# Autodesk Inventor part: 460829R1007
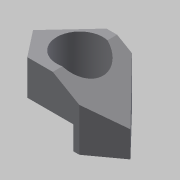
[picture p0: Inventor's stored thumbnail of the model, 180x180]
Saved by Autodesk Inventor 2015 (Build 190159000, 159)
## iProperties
Created: 2016-08
Part Number: 460829R1007
Material: 일반
Document SubType Name: Modeling
Designer: jio
Mass: 542.893 g
Surface Area: 683.408 cm^2
Volume: 542.893 cm^3
Density: 1 g/cm^3
Appearance: 기본값
Author: jio
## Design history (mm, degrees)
sketch "스케치1"
  geometry: L1 (34, 55)-(-9.387, 55); L2 (-9.387, 55)-(-70, -10); L3 (-70, -10)-(-34.842, -55); L4 (-34.842, -55)-(54, -55); L5 (54, -55)-(104.673, -18.184); L6 (104.673, -18.184)-(34, 55); C1 r 39.5 at (0, 0); 1 further point
  constraints: 12 end point, 1 centre point, 1 coincident, 1 horizontal, 1 parallel
  dimensions: "d0" = 79 diameter of C1; "d1" = 99 deg angle of L3 L2; "d2" = 128 deg angle of L4 L3; "d3" = 144 deg angle of L5 L4; "d4" = 134 deg angle of L6 L1; "d5" = 124 horizontal distance of L4.end L2.end; "d6" = 110 vertical distance of L3.end L1.end; "d7" = 45 vertical distance of L3.end L2.end; "d8" = 55 distance from line of L4 point (0, 0); "d9" = 70 horizontal distance of L2.end point (0, 0); "d10" = 104 horizontal distance of L1.start L2.end
extrude "돌출1" new body sketch "스케치1" distance "d11" = 100; taper "d12" = 0 deg
sketch "스케치3"
  geometry: L1 (-70, 15)-(44, 15); L2 (44, 15)-(44, -55); L3 (44, -55)-(-70, -55); L4 (-70, -55)-(-70, 15); 2 further points
  constraints: 8 end point, 2 parallel, 1 horizontal, 1 perpendicular, 1 point on line
  dimensions: "d13" = 70 distance between parallel lines of L1 L3; "d14" = 114 distance between parallel lines of L2 L4; "d15" = 55 distance from line of L3 point (0, 0)
extrude "돌출2" cut sketch "스케치3" distance "d16" = 40; taper "d17" = 0 deg
sketch "스케치4"
  geometry: L1 (43.515, 0)-(139.515, 0); L2 (139.515, 0)-(139.515, -55.426); L3 (139.515, -55.426)-(43.515, 0); 2 further points
  constraints: 6 end point, 1 coincident, 1 horizontal, 1 perpendicular
  dimensions: "d18" = 30 deg angle of L3 L1; "d19" = 96 distance of L1.start L1.end
extrude "돌출3" cut sketch "스케치4" stored distance "d20" = 40; taper "d21" = 0 deg
node "솔리드1"
